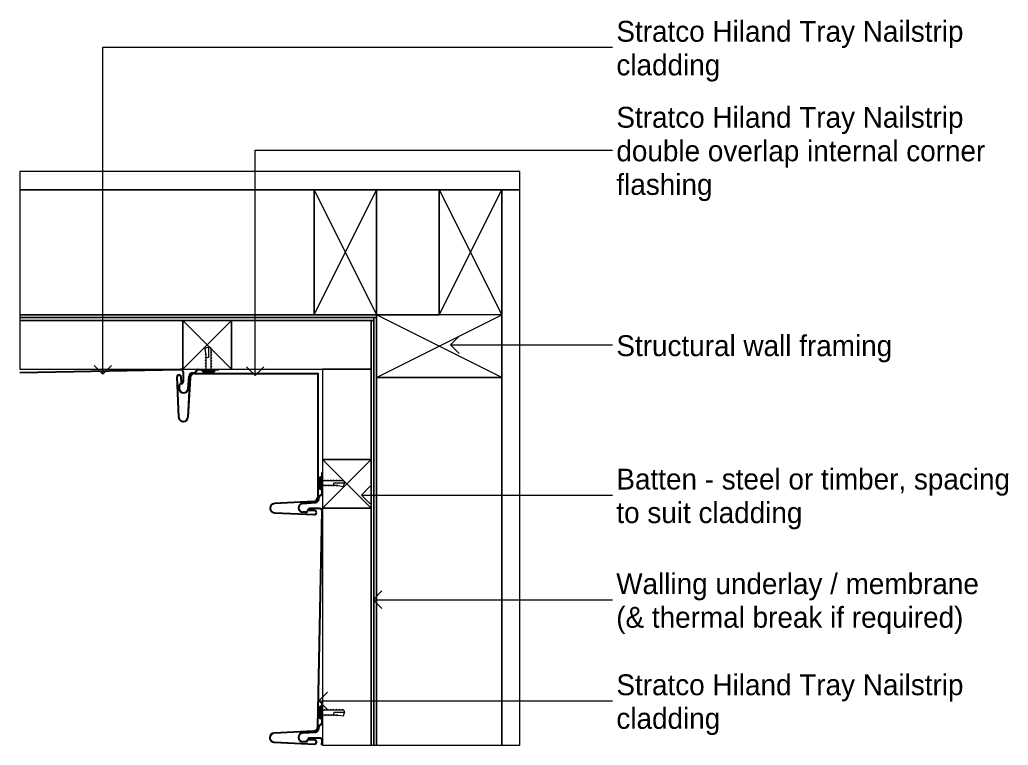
# Model space of a CAD drawing. Extents: x -2.36 to 6.66, y -3.72 to 4.13.
# Drawn here: x 1.924 to 2.635, y -3.412 to -2.891 of the extents above; entities that cross this region are included whole.
import ezdxf

# ---------------------------------------------------------------- set-up
doc = ezdxf.new("R2010")
doc.units = 0
for name, color, linetype in [('A-____-____-IDEN', 7, 'Continuous'), ('A-DETL-____-MEDM', 7, 'Continuous'), ('A-DETL-GENF-OTLN', 7, 'Continuous'), ('A-WALL-____-MCUT', 7, 'Continuous'), ('A-WALL-____-PATT', 7, 'Continuous'), ('A-WALL-FNSH-MCUT', 7, 'Continuous')]:
    doc.layers.add(name, color=color, linetype=linetype)

# ---------------------------------------------------------------- blocks, each defined once
blk = doc.blocks.new('DET_ST_Framing Detail Timber - 35x35 Batten-Detail Flashings - Hiland Nailstrip Corner')
at = {"layer": 'A-DETL-____-MEDM'}
for p, q in [((0.035, 0), (0, 0)), ((0, 0), (0, -0.035)), ((0.035, -0.035), (0.035, 0)), ((0, -0.035), (0.035, -0.035))]:
    blk.add_line(p, q, dxfattribs=at)
at = {"layer": 'A-DETL-GENF-OTLN'}
for p, q in [((0, -0.035), (0.035, 0)), ((0.035, -0.035), (0, 0))]:
    blk.add_line(p, q, dxfattribs=at)
blk = doc.blocks.new('Detail_Stratco_Hiland_Tray_Nailstrip_Double Overlap Int Corner - Rib Height 38mm_100mm Cover-Detail Flashings - Hiland Nailstrip Corner')
at = {"layer": 'A-DETL-GENF-OTLN'}
for p, q in [((-0.03456, 0.12852), (-0.00567, 0.12983)), ((-0.03454, 0.12802), (-0.00565, 0.12933)), ((-0.00634, 0.12), (-0.03464, 0.12149)), ((-0.00632, 0.1205), (-0.03461, 0.12198)), ((-0.00558, 0.12699), (-0.00976, 0.12687)), ((-0.00557, 0.12649), (-0.00974, 0.12637)), ((-0.0035, 0.117), (-0.0035, 0.0285)), ((-0.003, 0.117), (-0.003, 0.028)), ((-0.10352, 0.0595), (-0.10483, 0.03077)), ((-0.10302, 0.05948), (-0.10433, 0.03075)), ((-0.0955, 0.03126), (-0.09698, 0.05955)), ((-0.095, 0.03128), (-0.09649, 0.05958)), ((-0.10199, 0.03068), (-0.10187, 0.03486)), ((-0.10149, 0.03067), (-0.10137, 0.03484)), ((-0.0035, 0.0285), (-0.092, 0.0285)), ((-0.003, 0.028), (-0.092, 0.028))]:
    blk.add_line(p, q, dxfattribs=at)
for centre, radius, start, end in [((-0.03445, 0.125), 0.00352, 91.72283, 181.72823), ((-0.03445, 0.125), 0.00302, 91.65349, 181.72911), ((-0.00562, 0.12816), 0.00167, 1.69561, 91.73842), ((-0.00562, 0.12816), 0.00117, 1.68553, 91.57145), ((-0.00562, 0.12816), 0.00117, 271.72718, 1.75272), ((-0.00562, 0.12816), 0.00167, 271.72718, 1.74264), ((-0.03445, 0.125), 0.00352, 181.71763, 266.99932), ((-0.03445, 0.125), 0.00302, 181.71675, 266.99932), ((-0.0065, 0.11701), 0.0035, 359.8838, 86.99932), ((-0.0065, 0.11701), 0.003, 359.8838, 83.99932), ((-0.1, 0.05939), 0.00352, 88.26763, 178.27717), ((-0.1, 0.05939), 0.00302, 88.2636, 178.34651), ((-0.1, 0.05939), 0.00302, 3.00068, 88.27596), ((-0.1, 0.05939), 0.00352, 3.00068, 88.27823), ((-0.10316, 0.03072), 0.00167, 178.26158, 268.3107), ((-0.10316, 0.03072), 0.00117, 178.42855, 268.31762), ((-0.10316, 0.03072), 0.00167, 268.26367, 358.27281), ((-0.10316, 0.03072), 0.00117, 268.25044, 358.27282), ((-0.09202, 0.0316), 0.0035, 185.57222, 270.11622), ((-0.09202, 0.0316), 0.003, 186.00068, 270.1162)]:
    blk.add_arc(centre, radius, start, end, dxfattribs=at)
blk = doc.blocks.new('Detail Repeating_Stratco_Hiland_Tray_Nailstrip - Rib Height 38mm_165mm Coverage-V10-Detail Flashings - Hiland Nailstrip Corner')
at = {"layer": 'A-DETL-____-MEDM'}
for p, q in [((0.32648, 0.03459), (0.32517, 0.0057)), ((0.32698, 0.03457), (0.32567, 0.00568)), ((0.3345, 0.00635), (0.33302, 0.03464)), ((0.335, 0.00637), (0.33351, 0.03466)), ((0.32679, 0.01206), (0.32679, 0.01397)), ((0.32729, 0.01206), (0.32729, 0.01397)), ((0.32801, 0.00561), (0.32813, 0.00979)), ((0.32863, 0.00977), (0.32813, 0.00979)), ((0.32851, 0.0056), (0.32863, 0.00977)), ((0.3295, 0.002), (0.3295, 0.00924)), ((0.33, 0.002), (0.33, 0.00924)), ((0.33314, 0.01418), (0.3338, 0.00504)), ((0.33363, 0.01422), (0.33429, 0.00508)), ((0.49179, 0.01206), (0.49179, 0.01397)), ((0.49229, 0.01206), (0.49229, 0.01397)), ((0.4945, 0.002), (0.4945, 0.00924)), ((0.495, 0.002), (0.495, 0.00924)), ((0.49814, 0.01418), (0.4988, 0.00504)), ((0.49863, 0.01422), (0.49929, 0.00508)), ((0.32457, 0.00057), (0.32798, 0.0005)), ((0.32457, 0.00007), (0.32797, 0)), ((0.33662, 0.00291), (0.33757, 0.00291)), ((0.33662, 0.00241), (0.33757, 0.00241)), ((0.338, 0.00353), (0.49298, 0.0005)), ((0.338, 0.00303), (0.49297, 0)), ((0.34071, 0.0005), (0.35557, 0.0005)), ((0.35557, 0), (0.35557, 0.0005)), ((0.50162, 0.00291), (0.50257, 0.00291)), ((0.50162, 0.00241), (0.50257, 0.00241)), ((0.50571, 0.0005), (0.52057, 0.0005)), ((0.52057, 0), (0.52057, 0.0005)), ((0.34071, 0), (0.35557, 0)), ((0.50571, 0), (0.52057, 0))]:
    blk.add_line(p, q, dxfattribs=at)
for centre, radius, start, end in [((0.33, 0.03448), 0.00352, 88.27177, 178.27717), ((0.33, 0.03448), 0.00302, 88.27089, 178.34651), ((0.33, 0.03448), 0.00302, 3.00068, 88.28325), ((0.33, 0.03448), 0.00352, 3.00068, 88.28237), ((0.33022, 0.01397), 0.00342, 4.13153, 180), ((0.33022, 0.01397), 0.00292, 4.13153, 180), ((0.49522, 0.01397), 0.00342, 4.13153, 180), ((0.49522, 0.01397), 0.00292, 4.13153, 180), ((0.32869, 0.01206), 0.0019, 180, 262.83254), ((0.32869, 0.01206), 0.0014, 180, 260.84549), ((0.32856, 0.00924), 0.000939, 0, 96.36508), ((0.32856, 0.00924), 0.00144, 0, 93.57624), ((0.49369, 0.01206), 0.0019, 180, 262.83254), ((0.49369, 0.01206), 0.0014, 180, 260.84549), ((0.49356, 0.00924), 0.000939, 0, 96.36508), ((0.49356, 0.00924), 0.00144, 0, 93.57624), ((0.32684, 0.00565), 0.00167, 178.26158, 268.30439), ((0.32684, 0.00565), 0.00117, 178.42855, 268.31447), ((0.32684, 0.00565), 0.00167, 268.25736, 358.27282), ((0.32684, 0.00565), 0.00117, 268.24728, 358.27282), ((0.328, 0.002), 0.002, 270, 0), ((0.328, 0.002), 0.0015, 270, 360), ((0.33662, 0.00525), 0.00283, 184.13153, 270), ((0.33662, 0.00525), 0.00233, 184.13153, 270), ((0.33799, 0.00653), 0.0035, 183.00068, 270.1162), ((0.33799, 0.00653), 0.003, 186.00068, 270.1162), ((0.33757, 0.00107), 0.00185, 14.91043, 90), ((0.33757, 0.00107), 0.00135, 14.91043, 90), ((0.34071, 0.0019), 0.0019, 194.91043, 270), ((0.34071, 0.0019), 0.0014, 194.91043, 270), ((0.493, 0.002), 0.002, 270, 0), ((0.493, 0.002), 0.0015, 270, 360), ((0.50162, 0.00525), 0.00283, 184.13153, 270), ((0.50162, 0.00525), 0.00233, 184.13153, 270), ((0.50257, 0.00107), 0.00185, 14.91043, 90), ((0.50257, 0.00107), 0.00135, 14.91043, 90), ((0.50571, 0.0019), 0.0019, 194.91043, 270), ((0.50571, 0.0019), 0.0014, 194.91043, 270)]:
    blk.add_arc(centre, radius, start, end, dxfattribs=at)
at = {"layer": 'A-DETL-GENF-OTLN'}
for p, q in [((0.34399, 0.00222), (0.34344, 0.00128)), ((0.34345, 0.00129), (0.35255, 0.00129)), ((0.3521, 0.00058), (0.3439, 0.00058)), ((0.35201, 0.00222), (0.34399, 0.00222)), ((0.35255, 0.00129), (0.35201, 0.00222)), ((0.50899, 0.00222), (0.50844, 0.00128)), ((0.50845, 0.00129), (0.51755, 0.00129)), ((0.5171, 0.00058), (0.5089, 0.00058)), ((0.51701, 0.00222), (0.50899, 0.00222)), ((0.51755, 0.00129), (0.51701, 0.00222)), ((0.3455, -0.00228), (0.34625, -0.00205)), ((0.3455, -0.00438), (0.34625, -0.00414)), ((0.3455, -0.00648), (0.34625, -0.00624)), ((0.34625, -0.01102), (0.34625, -0.00022)), ((0.34975, -0.0153), (0.34975, -0.00022)), ((0.34975, -0.00201), (0.3505, -0.00177)), ((0.34975, -0.00411), (0.3505, -0.00387)), ((0.34975, -0.00621), (0.3505, -0.00597)), ((0.5105, -0.00228), (0.51125, -0.00205)), ((0.5105, -0.00438), (0.51125, -0.00414)), ((0.5105, -0.00648), (0.51125, -0.00624)), ((0.51125, -0.01102), (0.51125, -0.00022)), ((0.51475, -0.0153), (0.51475, -0.00022)), ((0.51475, -0.00201), (0.5155, -0.00177)), ((0.51475, -0.00411), (0.5155, -0.00387)), ((0.51475, -0.00621), (0.5155, -0.00597)), ((0.3455, -0.00858), (0.34625, -0.00834)), ((0.3455, -0.01068), (0.34625, -0.01044)), ((0.34625, -0.01102), (0.34568, -0.01509)), ((0.348, -0.00832), (0.34625, -0.00782)), ((0.348, -0.01594), (0.348, -0.00832)), ((0.34975, -0.0083), (0.3505, -0.00807)), ((0.34975, -0.0104), (0.3505, -0.01016)), ((0.34975, -0.0125), (0.3505, -0.01226)), ((0.5105, -0.00858), (0.51125, -0.00834)), ((0.5105, -0.01068), (0.51125, -0.01044)), ((0.51125, -0.01102), (0.51068, -0.01509)), ((0.513, -0.00832), (0.51125, -0.00782)), ((0.513, -0.01594), (0.513, -0.00832)), ((0.51475, -0.0083), (0.5155, -0.00807)), ((0.51475, -0.0104), (0.5155, -0.01016)), ((0.51475, -0.0125), (0.5155, -0.01226)), ((0.34568, -0.01509), (0.348, -0.01594)), ((0.34975, -0.0153), (0.348, -0.01594)), ((0.34975, -0.0146), (0.3505, -0.01436)), ((0.51068, -0.01509), (0.513, -0.01594)), ((0.51475, -0.0153), (0.513, -0.01594)), ((0.51475, -0.0146), (0.5155, -0.01436))]:
    blk.add_line(p, q, dxfattribs=at)
for centre, radius, start, end in [((0.3439, 0.00108), 0.0005, 156.33018, 270), ((0.34545, -0.00022), 0.0008, 0, 90), ((0.35055, -0.00022), 0.0008, 90, 180), ((0.3521, 0.00108), 0.0005, 270, 23.66982), ((0.5089, 0.00108), 0.0005, 156.33018, 270), ((0.51045, -0.00022), 0.0008, 360, 90), ((0.51555, -0.00022), 0.0008, 90, 180), ((0.5171, 0.00108), 0.0005, 270, 23.66982)]:
    blk.add_arc(centre, radius, start, end, dxfattribs=at)
blk = doc.blocks.new('DET_ST_Framing Detail Timber - 35x35 Batten-V8-Detail Flashings - Hiland Nailstrip Corner')
at = {"layer": 'A-DETL-____-MEDM'}
for p, q in [((0.035, 0.035), (0, 0.035)), ((0, 0.035), (0, 0)), ((0.035, 0), (0.035, 0.035)), ((0, 0), (0.035, 0))]:
    blk.add_line(p, q, dxfattribs=at)
at = {"layer": 'A-DETL-GENF-OTLN'}
for p, q in [((0, 0.035), (0.035, 0)), ((0.035, 0.035), (0, 0))]:
    blk.add_line(p, q, dxfattribs=at)
blk = doc.blocks.new('Detail Repeating_Stratco_Hiland_Tray_Nailstrip - Rib Height 38mm_165mm Coverage-V11-Detail Flashings - Hiland Nailstrip Corner')
at = {"layer": 'A-DETL-____-MEDM'}
for p, q in [((0.50571, 0), (0.52057, 0)), ((0.52057, 0), (0.52057, -0.0005)), ((0.37729, -0.00226), (0.49297, 0)), ((0.37729, -0.00276), (0.49298, -0.0005)), ((0.4945, -0.002), (0.4945, -0.00924)), ((0.495, -0.002), (0.495, -0.00924)), ((0.49814, -0.01418), (0.4988, -0.00504)), ((0.49863, -0.01422), (0.49929, -0.00508)), ((0.50162, -0.00241), (0.50257, -0.00241)), ((0.50162, -0.00291), (0.50257, -0.00291)), ((0.50571, -0.0005), (0.52057, -0.0005)), ((0.49179, -0.01206), (0.49179, -0.01397)), ((0.49229, -0.01206), (0.49229, -0.01397))]:
    blk.add_line(p, q, dxfattribs=at)
for centre, radius, start, end in [((0.493, -0.002), 0.002, 360, 90), ((0.50571, -0.0019), 0.0019, 90, 165.08957), ((0.493, -0.002), 0.0015, 0, 90), ((0.50162, -0.00525), 0.00283, 90, 175.86847), ((0.50162, -0.00525), 0.00233, 90, 175.86847), ((0.50257, -0.00107), 0.00135, 270, 345.08957), ((0.50257, -0.00107), 0.00185, 270, 345.08957), ((0.50571, -0.0019), 0.0014, 90, 165.08957), ((0.49369, -0.01206), 0.0019, 97.16746, 180), ((0.49522, -0.01397), 0.00342, 180, 355.86847), ((0.49369, -0.01206), 0.0014, 99.15451, 180), ((0.49522, -0.01397), 0.00292, 180, 355.86847), ((0.49356, -0.00924), 0.000939, 263.63492, 0), ((0.49356, -0.00924), 0.00144, 266.42376, 0)]:
    blk.add_arc(centre, radius, start, end, dxfattribs=at)
at = {"layer": 'A-DETL-GENF-OTLN'}
for p, q in [((0.51068, 0.01509), (0.513, 0.01594)), ((0.51125, 0.01102), (0.51068, 0.01509)), ((0.513, 0.01594), (0.513, 0.00832)), ((0.51475, 0.0153), (0.513, 0.01594)), ((0.51475, 0.0153), (0.51475, 0.00022)), ((0.51475, 0.0146), (0.5155, 0.01436)), ((0.5105, 0.01068), (0.51125, 0.01044)), ((0.5105, 0.00858), (0.51125, 0.00834)), ((0.51125, 0.01102), (0.51125, 0.00022)), ((0.513, 0.00832), (0.51125, 0.00782)), ((0.51475, 0.0125), (0.5155, 0.01226)), ((0.51475, 0.0104), (0.5155, 0.01016)), ((0.51475, 0.0083), (0.5155, 0.00807)), ((0.5105, 0.00648), (0.51125, 0.00624)), ((0.5105, 0.00438), (0.51125, 0.00414)), ((0.5105, 0.00228), (0.51125, 0.00205)), ((0.51475, 0.00621), (0.5155, 0.00597)), ((0.51475, 0.00411), (0.5155, 0.00387)), ((0.51475, 0.00201), (0.5155, 0.00177)), ((0.50899, -0.00222), (0.50844, -0.00128)), ((0.50845, -0.00129), (0.51755, -0.00129)), ((0.5171, -0.00058), (0.5089, -0.00058)), ((0.51701, -0.00222), (0.50899, -0.00222)), ((0.51755, -0.00129), (0.51701, -0.00222))]:
    blk.add_line(p, q, dxfattribs=at)
for centre, radius, start, end in [((0.51045, 0.00022), 0.0008, 270, 360), ((0.51555, 0.00022), 0.0008, 180, 270), ((0.5089, -0.00108), 0.0005, 90, 203.66982), ((0.5171, -0.00108), 0.0005, 336.33018, 90)]:
    blk.add_arc(centre, radius, start, end, dxfattribs=at)
blk = doc.blocks.new('DET_ST_Framing Detail Timber - 45x90-Detail Flashings - Hiland Nailstrip Corner')
at = {"layer": 'A-DETL-____-MEDM'}
for p, q in [((0.09, 0.045), (0, 0.045)), ((0.09, 0), (0.09, 0.045)), ((0, 0), (0.09, 0))]:
    blk.add_line(p, q, dxfattribs=at)
at = {"layer": 'A-DETL-GENF-OTLN'}
for p, q in [((0, 0.045), (0.09, 0)), ((0.09, 0.045), (0, 0))]:
    blk.add_line(p, q, dxfattribs=at)
blk = doc.blocks.new('DET_ST_Framing Detail Timber - 45x90-V12-Detail Flashings - Hiland Nailstrip Corner')
at = {"layer": 'A-DETL-____-MEDM'}
for p, q in [((0.09, 0.045), (0, 0.045)), ((0, 0.045), (0, 0)), ((0.09, 0), (0.09, 0.045)), ((0, 0), (0.09, 0))]:
    blk.add_line(p, q, dxfattribs=at)
at = {"layer": 'A-DETL-GENF-OTLN'}
for p, q in [((0, 0.045), (0.09, 0)), ((0.09, 0.045), (0, 0))]:
    blk.add_line(p, q, dxfattribs=at)

msp = doc.modelspace()

# ---------------------------------------------------------------- linework, layer by layer
at = {"layer": 'A-____-____-IDEN'}
for p, q in [((1.98341, -2.91063), (2.35011, -2.91063)), ((1.98341, -3.14572), (1.98341, -2.91063)), ((2.09304, -2.98451), (2.35011, -2.98451)), ((2.09304, -3.14663), (2.09304, -2.98451)), ((2.2334, -3.12457), (2.23965, -3.11832)), ((2.2334, -3.12457), (2.23965, -3.13082)), ((2.2334, -3.12457), (2.29593, -3.12457)), ((2.29593, -3.12457), (2.35011, -3.12457)), ((1.98341, -3.14572), (1.97716, -3.13947)), ((1.98341, -3.14572), (1.98966, -3.13947)), ((2.09304, -3.14663), (2.08679, -3.14038)), ((2.09304, -3.14663), (2.09929, -3.14038)), ((2.16948, -3.23254), (2.17573, -3.22629)), ((2.16948, -3.23254), (2.17573, -3.23879)), ((2.16948, -3.23254), (2.20713, -3.23254)), ((2.20713, -3.23254), (2.35011, -3.23254)), ((2.17794, -3.30779), (2.18419, -3.30154)), ((2.17794, -3.30779), (2.18419, -3.31404)), ((2.17794, -3.30779), (2.20713, -3.30779)), ((2.20713, -3.30779), (2.35011, -3.30779)), ((2.13883, -3.38045), (2.14508, -3.3742)), ((2.13883, -3.38045), (2.14508, -3.3867)), ((2.13883, -3.38045), (2.35011, -3.38045))]:
    msp.add_line(p, q, dxfattribs=at)
at = {"layer": 'A-WALL-____-MCUT'}
for p, q in [((2.13534, -3.013), (1.92364, -3.013)), ((2.22534, -3.013), (2.18034, -3.013)), ((2.13534, -3.103), (1.92364, -3.103)), ((2.17834, -3.105), (1.92364, -3.105)), ((2.04103, -3.107), (1.92364, -3.107)), ((2.17634, -3.107), (2.07603, -3.107)), ((2.17634, -3.107), (2.17634, -3.207)), ((2.17834, -3.105), (2.17834, -3.41243)), ((1.92364, -3.142), (2.04103, -3.142)), ((2.07603, -3.142), (2.14134, -3.142)), ((2.14134, -3.142), (2.14134, -3.207)), ((2.18034, -3.148), (2.18034, -3.41243)), ((2.27034, -3.148), (2.27034, -3.41243)), ((2.14134, -3.242), (2.14134, -3.41243)), ((2.17634, -3.242), (2.17634, -3.41243))]:
    msp.add_line(p, q, dxfattribs=at)
at = {"layer": 'A-WALL-____-PATT'}
for p, q in [((2.28334, -3), (1.92364, -3)), ((1.92364, -3), (1.92364, -3.013)), ((2.28334, -3.013), (2.28334, -3)), ((1.92364, -3.013), (2.18034, -3.013)), ((2.13534, -3.013), (1.92364, -3.013)), ((1.92364, -3.013), (1.92364, -3.103)), ((2.13534, -3.103), (2.13534, -3.013)), ((2.18034, -3.013), (2.21011, -3.013)), ((2.22534, -3.013), (2.18034, -3.013)), ((2.18034, -3.013), (2.18034, -3.103)), ((2.21011, -3.013), (2.28334, -3.013)), ((2.22534, -3.103), (2.22534, -3.013)), ((2.28334, -3.013), (2.27034, -3.013)), ((2.27034, -3.013), (2.27034, -3.41243)), ((2.28334, -3.41243), (2.28334, -3.013)), ((1.92364, -3.103), (2.13534, -3.103)), ((1.92364, -3.103), (1.92364, -3.103)), ((2.18034, -3.103), (1.92364, -3.103)), ((1.92364, -3.103), (1.92364, -3.105)), ((1.92364, -3.105), (2.17834, -3.105)), ((2.17834, -3.105), (1.92364, -3.105)), ((1.92364, -3.105), (1.92364, -3.107)), ((2.04103, -3.107), (1.92364, -3.107)), ((1.92364, -3.107), (1.92364, -3.142)), ((1.92364, -3.107), (2.17634, -3.107)), ((2.04103, -3.142), (2.04103, -3.107)), ((2.17634, -3.107), (2.07603, -3.107)), ((2.07603, -3.107), (2.07603, -3.142)), ((2.17634, -3.142), (2.17634, -3.107)), ((2.17634, -3.107), (2.17834, -3.107)), ((2.17834, -3.107), (2.17634, -3.107)), ((2.17634, -3.107), (2.17634, -3.41243)), ((2.17834, -3.105), (2.18034, -3.105)), ((2.17834, -3.107), (2.17834, -3.105)), ((2.18034, -3.105), (2.17834, -3.105)), ((2.17834, -3.105), (2.17834, -3.148)), ((2.17834, -3.41243), (2.17834, -3.107)), ((2.18034, -3.103), (2.18034, -3.103)), ((2.18034, -3.103), (2.22534, -3.103)), ((2.18034, -3.105), (2.18034, -3.103)), ((2.18034, -3.41243), (2.18034, -3.105)), ((1.92364, -3.142), (2.04103, -3.142)), ((2.07603, -3.142), (2.14134, -3.142)), ((2.14134, -3.142), (2.17634, -3.142)), ((2.17634, -3.142), (2.14134, -3.142)), ((2.14134, -3.142), (2.14134, -3.207)), ((2.17634, -3.41243), (2.17634, -3.142)), ((2.17834, -3.148), (2.17834, -3.41243)), ((2.27034, -3.148), (2.18034, -3.148)), ((2.18034, -3.148), (2.18034, -3.41243)), ((2.27034, -3.41243), (2.27034, -3.148)), ((2.14134, -3.207), (2.17634, -3.207)), ((2.17634, -3.207), (2.17634, -3.242)), ((2.17634, -3.242), (2.14134, -3.242)), ((2.14134, -3.242), (2.14134, -3.41243)), ((2.14134, -3.41243), (2.17634, -3.41243)), ((2.17634, -3.41243), (2.17834, -3.41243)), ((2.17834, -3.41243), (2.18034, -3.41243)), ((2.18034, -3.41243), (2.27034, -3.41243)), ((2.27034, -3.41243), (2.28334, -3.41243))]:
    msp.add_line(p, q, dxfattribs=at)
at = {"layer": 'A-WALL-FNSH-MCUT'}
for p, q in [((2.28334, -3), (1.92364, -3)), ((2.28334, -3.41243), (2.28334, -3))]:
    msp.add_line(p, q, dxfattribs=at)

# ---------------------------------------------------------------- block references
at = {"layer": 'A-DETL-GENF-OTLN'}
for name, p, rotation in [('DET_ST_Framing Detail Timber - 45x90-V12-Detail Flashings - Hiland Nailstrip Corner', (2.18034, -3.103), 89.9999999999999), ('DET_ST_Framing Detail Timber - 45x90-Detail Flashings - Hiland Nailstrip Corner', (2.27034, -3.103), 89.9999999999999), ('DET_ST_Framing Detail Timber - 45x90-V12-Detail Flashings - Hiland Nailstrip Corner', (2.27034, -3.103), 180), ('Detail_Stratco_Hiland_Tray_Nailstrip_Double Overlap Int Corner - Rib Height 38mm_100mm Cover-Detail Flashings - Hiland Nailstrip Corner', (2.16634, -3.142), 89.9999999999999), ('DET_ST_Framing Detail Timber - 35x35 Batten-Detail Flashings - Hiland Nailstrip Corner', (2.14134, -3.242), 90.00000000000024), ('Detail Repeating_Stratco_Hiland_Tray_Nailstrip - Rib Height 38mm_165mm Coverage-V10-Detail Flashings - Hiland Nailstrip Corner', (2.14134, -3.737), 89.99999999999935)]:
    msp.add_blockref(name, p, dxfattribs=dict(at, rotation=rotation))
for name, p in [('DET_ST_Framing Detail Timber - 35x35 Batten-V8-Detail Flashings - Hiland Nailstrip Corner', (2.04103, -3.142)), ('Detail Repeating_Stratco_Hiland_Tray_Nailstrip - Rib Height 38mm_165mm Coverage-V11-Detail Flashings - Hiland Nailstrip Corner', (1.54634, -3.142))]:
    msp.add_blockref(name, p, dxfattribs=at)

# ---------------------------------------------------------------- texts
at = {"layer": 'A-____-____-IDEN'}
for s, p in [('Stratco Hiland Tray Nailstrip', (2.35282, -2.90665)), ('cladding', (2.35282, -2.9308)), ('Stratco Hiland Tray Nailstrip', (2.35282, -2.96846)), ('double overlap internal corner', (2.35282, -2.9926)), ('flashing', (2.35282, -3.01675)), ('Structural wall framing', (2.35282, -3.13267)), ('Batten - steel or timber, spacing', (2.35282, -3.22857)), ('to suit cladding', (2.35282, -3.25271)), ('Walling underlay / membrane', (2.35272, -3.30381)), ('(& thermal break if required)', (2.35272, -3.32796)), ('Stratco Hiland Tray Nailstrip', (2.35282, -3.37648)), ('cladding', (2.35282, -3.40062))]:
    msp.add_text(s, height=0.015, dxfattribs=at).set_placement(p)

doc.saveas('drawing.dxf')
